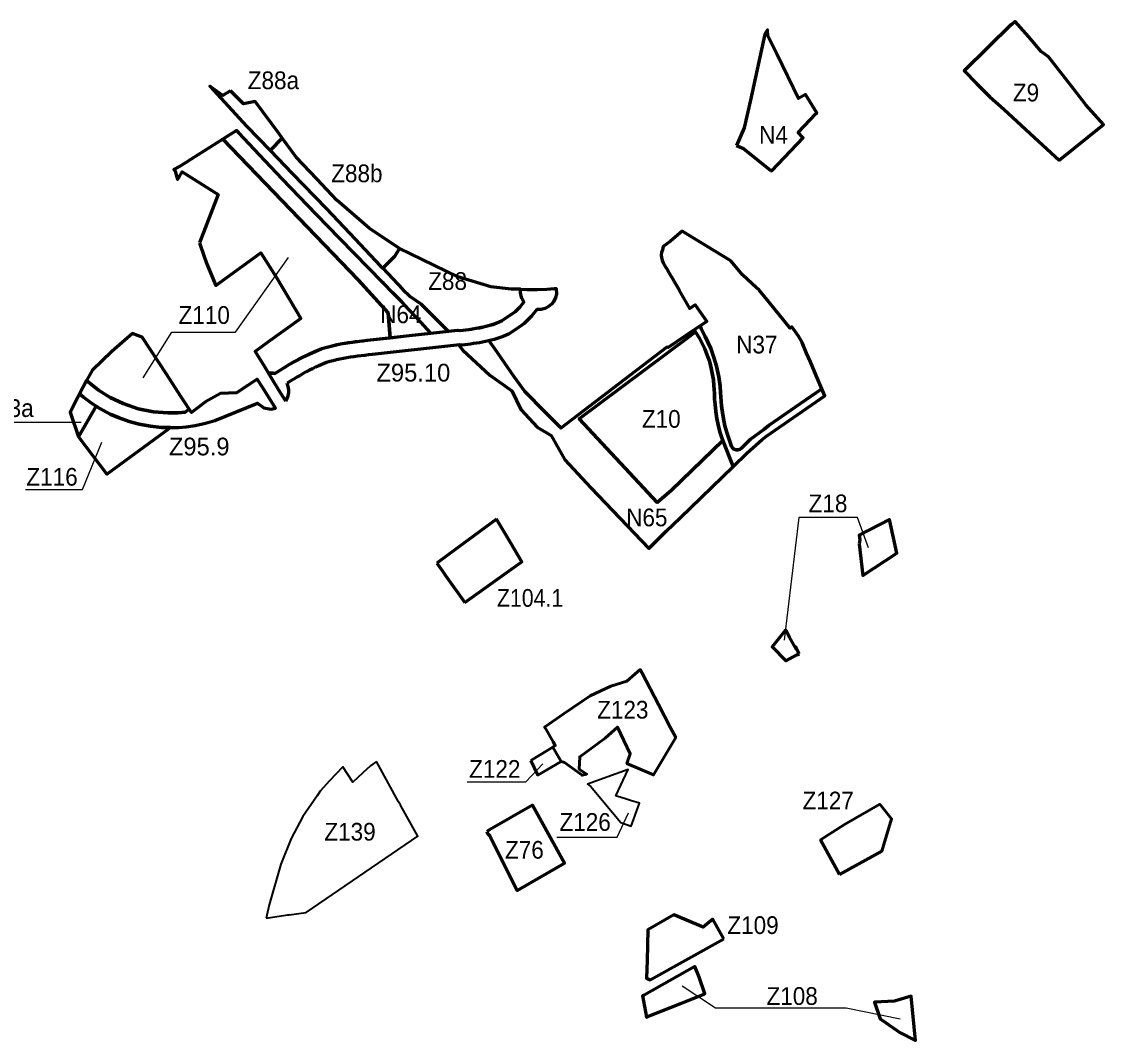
# Model space of a CAD drawing. Extents: x -650277 to -643425, y -1073980 to -1066720.
# Drawn here: x -647467 to -646003, y -1073134 to -1071755 of the extents above; entities that cross this region are included whole.
import ezdxf

# ---------------------------------------------------------------- set-up
doc = ezdxf.new("R2010")
doc.units = 0
doc.header["$LTSCALE"] = 9.6
for name, color, linetype, lineweight in [('1', 7, 'Continuous', 60), ('15', 7, 'Continuous', 60), ('18', 7, 'Continuous', 60), ('2', 7, 'Continuous', 40), ('24', 7, 'Continuous', 60), ('30', 7, 'Continuous', 60), ('34', 7, 'Continuous', 60), ('35', 7, 'Continuous', 60), ('40', 7, 'Continuous', 60), ('42', 7, 'Continuous', 60), ('45', 7, 'Continuous', 60), ('59', 7, 'Continuous', 25), ('60', 7, 'Continuous', 60), ('63', 7, 'Continuous', 25), ('7', 7, 'Continuous', 60)]:
    doc.layers.add(name, color=color, linetype=linetype, lineweight=lineweight)

msp = doc.modelspace()

# ---------------------------------------------------------------- linework, layer by layer
at = {"layer": '1'}
msp.add_line((-646417.787, -1072612.168), (-646414.77, -1072610.61), dxfattribs=at)
for points in [[(-646102.04, -1071906.4), (-646068.317, -1071937.555), (-646062.91, -1071942.55), (-646002.93, -1071893.984), (-646026.64, -1071867.44), (-646043.49, -1071845.87), (-646077.32, -1071802.59), (-646087, -1071795), (-646104.5, -1071774.86), (-646122.16, -1071754.78), (-646127.12, -1071759.15), (-646127.84, -1071758.53), (-646191.57, -1071821.44), (-646174.69, -1071838.69), (-646156.59, -1071856.53), (-646137.74, -1071873.31)], [(-646606.848, -1072405.785), (-646587.666, -1072389.082), (-646518.208, -1072321.92), (-646519.417, -1072318.408), (-646522.007, -1072309.932), (-646524.282, -1072300.849), (-646526, -1072292.201), (-646527.5, -1072282.657), (-646528.566, -1072273.308), (-646529.182, -1072265.941), (-646529.607, -1072258.124), (-646530.188, -1072247.442), (-646530.892, -1072239.747), (-646531.93, -1072232.861), (-646533.286, -1072226.031), (-646535.344, -1072217.844), (-646536.772, -1072213.218), (-646539.168, -1072206.122), (-646539.168, -1072206.122), (-646542.484, -1072197.985), (-646546.09, -1072190.428), (-646549.793, -1072183.38), (-646554.56, -1072175.629), (-646555.051, -1072174.933), (-646563.299, -1072181.091), (-646710.684, -1072291.133), (-646712.634, -1072292.59)], [(-646333.34, -1072461.67), (-646328.45, -1072504.81), (-646282.47, -1072474.34), (-646292.44, -1072428.89), (-646333.33, -1072450.12), (-646332.68, -1072456.19)]]:
    msp.add_lwpolyline(points, close=True, dxfattribs=at)
for points in [[(-647184.81, -1071848.61), (-647185.62, -1071849.12), (-647194.96, -1071854.93), (-647205.62, -1071847.24), (-647212.66, -1071842.15), (-647163.08, -1071896.13), (-647131.146, -1071929.146)], [(-647131.146, -1071929.146), (-647114.479, -1071912.479), (-647118.79, -1071906.59), (-647151.07, -1071863.08), (-647167.15, -1071866.22), (-647184.81, -1071848.61)], [(-646996.8, -1072034.35), (-647040.89, -1071996.58), (-647067.53, -1071967.54), (-647095.51, -1071938.39), (-647114.479, -1071912.479), (-647131.146, -1071929.146), (-647101.07, -1071960.24)], [(-647101.07, -1071960.24), (-647055.16, -1072007.74), (-647023.04, -1072041.63), (-646981.35, -1072085.77), (-646978.602, -1072088.66), (-646962.041, -1072072.379), (-646956.04, -1072061.95), (-646996.8, -1072034.35)], [(-646420.36, -1072601.78), (-646427.95, -1072588.07), (-646432.57, -1072579.75), (-646433.36, -1072578.45), (-646451.458, -1072601.008), (-646433.024, -1072620.04), (-646417.787, -1072612.168)], [(-646414.77, -1072610.61), (-646419.11, -1072602.03), (-646419.47, -1072601.31), (-646419.02, -1072604.18), (-646420.36, -1072601.78)]]:
    msp.add_lwpolyline(points, dxfattribs=at)
at = {"layer": '1', "lineweight": 53}
for points in [[(-646737.05, -1072756.4), (-646732.5, -1072757.63), (-646708.65, -1072775.02), (-646702.45, -1072773.39), (-646712.46, -1072766.76), (-646711.79, -1072750.02), (-646677.39, -1072724.85), (-646660.89, -1072709.97), (-646643.36, -1072746.04), (-646647.93, -1072759.01), (-646612.11, -1072774.56), (-646581.92, -1072723.91), (-646589.37, -1072709.83), (-646605.23, -1072679.37), (-646627.32, -1072636.95), (-646629.86, -1072632.07), (-646648.27, -1072647.48), (-646669.6, -1072654.53), (-646697.89, -1072667.65)], [(-646697.89, -1072667.65), (-646732.95, -1072691.68), (-646759.491, -1072709.878), (-646757.5, -1072713.3), (-646747.87, -1072729.85), (-646744.94, -1072734.88), (-646748.3, -1072737.01), (-646737.05, -1072756.4)]]:
    msp.add_lwpolyline(points, dxfattribs=at)
for points in [[(-646778.2, -1072755.19), (-646755.1, -1072741.28), (-646748.3, -1072737.01), (-646737.05, -1072756.4), (-646768.74, -1072774.78)], [(-646360.22, -1072909.57), (-646303.02, -1072877.74), (-646289.63, -1072834.04), (-646305.56, -1072814.43), (-646353.25, -1072841.63), (-646385.86, -1072862.59)]]:
    msp.add_lwpolyline(points, close=True, dxfattribs=at)
at = {"layer": '1', "lineweight": 25}
msp.add_lwpolyline([(-646864.278, -1072783.783), (-646784.878, -1072783.783), (-646761.687, -1072759.411)], dxfattribs=at)
at = {"layer": '1', "lineweight": 40}
for points in [[(-646653.02, -1072806.07), (-646663.07, -1072803.04), (-646663.07, -1072803.04), (-646646.12, -1072767.32), (-646646.31, -1072767.388), (-646701.12, -1072787.08), (-646697.09, -1072790.03), (-646656.36, -1072839.08)], [(-646656.36, -1072839.08), (-646642.404, -1072844.195), (-646631.08, -1072812.68), (-646643.01, -1072809.08), (-646651.11, -1072806.64), (-646653.02, -1072806.07)]]:
    msp.add_lwpolyline(points, dxfattribs=at)
at = {"layer": '15'}
msp.add_lwpolyline([(-646529.182, -1072265.941), (-646528.566, -1072273.308), (-646527.5, -1072282.657), (-646526, -1072292.201), (-646524.282, -1072300.849), (-646522.007, -1072309.932), (-646519.417, -1072318.408), (-646518.208, -1072321.92), (-646504.244, -1072357.026), (-646485.656, -1072338.908), (-646473.069, -1072327.765), (-646465.227, -1072321.127), (-646459.03, -1072316.137), (-646380.12, -1072261.44), (-646384.056, -1072252.138), (-646420.085, -1072276.737), (-646455.557, -1072301.131), (-646462.79, -1072306.784), (-646480.923, -1072320.667), (-646486.273, -1072325.526), (-646492.813, -1072332.07), (-646494.794, -1072333.558), (-646497.569, -1072334.55), (-646500.244, -1072334.45), (-646503.018, -1072333.459), (-646504.802, -1072331.971), (-646506.189, -1072329.889), (-646509.954, -1072319.377), (-646512.729, -1072311.048), (-646515.305, -1072301.925), (-646516.692, -1072294.983), (-646518.079, -1072287.051), (-646519.756, -1072274.861), (-646521.051, -1072256.707), (-646521.646, -1072248.378), (-646523.628, -1072235.883), (-646526.798, -1072221.011), (-646530.167, -1072209.31), (-646534.527, -1072197.411), (-646541.822, -1072181.102), (-646547.606, -1072170.835), (-646548.676, -1072166.737), (-646556.693, -1072172.16), (-646555.051, -1072174.933), (-646554.56, -1072175.629), (-646549.793, -1072183.38), (-646546.09, -1072190.428), (-646542.484, -1072197.985), (-646539.168, -1072206.122), (-646536.772, -1072213.218), (-646535.344, -1072217.844), (-646533.286, -1072226.031), (-646531.93, -1072232.861), (-646530.892, -1072239.747), (-646530.188, -1072247.442), (-646529.607, -1072258.124)], close=True, dxfattribs=at)
at = {"layer": '18'}
msp.add_lwpolyline([(-646837.81, -1072851.3), (-646836.5, -1072853.76), (-646833.67, -1072857.15), (-646824.89, -1072874.66), (-646796.68, -1072930.92), (-646732.28, -1072894.29), (-646775.85, -1072815.39), (-646834.08, -1072849.15)], close=True, dxfattribs=at)
at = {"layer": '2'}
for points in [[(-646987.154, -1072756.377), (-646995.02, -1072762.45), (-647005.249, -1072771.938), (-647019.06, -1072784.57), (-647032.7, -1072763.68), (-647050.492, -1072782.771)], [(-646954.7, -1072815.232), (-646957.105, -1072810.92), (-646987.154, -1072756.377)], [(-647050.492, -1072782.771), (-647063.04, -1072796.74), (-647067.22, -1072802.77), (-647086.65, -1072830.76), (-647102.38, -1072860.7), (-647116.33, -1072895.3)], [(-647136.39, -1072968.63), (-647110.32, -1072964.56), (-647107.01, -1072964.04), (-647105.4, -1072963.84), (-647082.36, -1072960.95), (-646931.1, -1072857.55), (-646954.51, -1072815.63), (-646954.7, -1072815.232)], [(-647116.33, -1072895.3), (-647132.47, -1072950.4), (-647136.39, -1072968.63)]]:
    msp.add_lwpolyline(points, dxfattribs=at)
at = {"layer": '24'}
for points in [[(-647226.41, -1072054.11), (-647219.64, -1072074.29), (-647216.23, -1072084.14), (-647204.78, -1072110.92), (-647204.38, -1072111.87), (-647143.76, -1072067.69), (-647122.33, -1072101.34), (-647089.54, -1072156.53), (-647134.17, -1072188.95), (-647151.05, -1072201.21), (-647138.65, -1072221.5), (-647133, -1072230.754), (-647124.81, -1072231.168), (-647104.989, -1072219.005), (-647082.249, -1072206.591), (-647060.973, -1072197.439), (-647035.515, -1072191.104), (-647010.148, -1072187.308), (-646995.137, -1072185.597), (-646968.503, -1072182.672), (-646971.283, -1072148.82), (-647011.762, -1072104.502), (-647194.903, -1071913.941), (-647238.1, -1071941), (-647245.71, -1071945.77), (-647253.67, -1071950.76), (-647261.12, -1071954.82), (-647259.7, -1071957.06), (-647256.53, -1071968.64), (-647253.85, -1071964.38), (-647249.92, -1071958.12), (-647201.53, -1071988.71)], [(-647390.58, -1072316.75), (-647366.505, -1072275.41), (-647372.858, -1072271.363), (-647383.813, -1072263.219), (-647389.072, -1072258.845), (-647391.3, -1072263.04), (-647401.88, -1072283.4)], [(-647390.58, -1072316.75), (-647351.86, -1072367.52), (-647269.52, -1072307.17), (-647265.793, -1072304.439), (-647271.395, -1072304.452), (-647278.108, -1072304.147), (-647292.715, -1072302.646), (-647308.157, -1072299.786), (-647321.953, -1072296.073), (-647335.382, -1072291.341), (-647347.369, -1072286.111), (-647361.521, -1072278.584), (-647366.505, -1072275.41)]]:
    msp.add_lwpolyline(points, close=True, dxfattribs=at)
msp.add_arc((-646767.624, -1072120.384), 24.428, 264.28146, 264.89913, dxfattribs=at)
at = {"layer": '30'}
for points in [[(-646824.42, -1072428.58), (-646878.91, -1072468.54), (-646905.18, -1072487.8)], [(-646867.283, -1072540.984), (-646791.569, -1072487.198), (-646790.354, -1072486.136), (-646810.77, -1072451.09), (-646824.42, -1072428.58)], [(-646905.18, -1072487.8), (-646898.1, -1072498.02), (-646893.64, -1072504.45), (-646867.283, -1072540.984)]]:
    msp.add_lwpolyline(points, dxfattribs=at)
at = {"layer": '34'}
for points in [[(-646574.156, -1073083.691), (-646542.62, -1073071.1), (-646550.01, -1073048.55), (-646552.79, -1073041.53), (-646555.79, -1073033.92), (-646624.69, -1073072.66), (-646626.967, -1073073.918), (-646621.38, -1073102.66), (-646620.19, -1073102.14), (-646618.56, -1073101.42)], [(-646298.029, -1073109.723), (-646278.38, -1073123.25), (-646257.09, -1073134.01), (-646262.94, -1073074.15), (-646285.77, -1073081.01), (-646312.87, -1073082.4), (-646305.18, -1073104.8)]]:
    msp.add_lwpolyline(points, close=True, dxfattribs=at)
at = {"layer": '35'}
for points in [[(-647246.563, -1072270.214), (-647251.85, -1072262.12), (-647271.38, -1072232.23), (-647304.32, -1072181.81), (-647310.33, -1072179.58), (-647317.33, -1072176.99), (-647345.42, -1072201.58), (-647372.1, -1072226.89), (-647375.551, -1072233.387), (-647379.422, -1072240.675), (-647363.317, -1072253.632), (-647347.382, -1072263.623), (-647330.032, -1072271.935), (-647309.416, -1072278.875), (-647288.769, -1072283.003), (-647269.579, -1072284.489), (-647255.671, -1072284.192), (-647246.206, -1072283.328), (-647240.55, -1072279.42)], [(-646516.7, -1072996.65), (-646531.46, -1072970.12), (-646544.68, -1072980.62), (-646584.23, -1072964.22), (-646619.48, -1072984.34), (-646620.71, -1073025.49), (-646621.44, -1073049.79), (-646616.55, -1073052.21)]]:
    msp.add_lwpolyline(points, close=True, dxfattribs=at)
at = {"layer": '40'}
msp.add_lwpolyline([(-646507.28, -1072078.4), (-646530.073, -1072064.559), (-646573.05, -1072038.46), (-646588.75, -1072052.06), (-646598.827, -1072059.244), (-646599.86, -1072063.71), (-646601, -1072067.55), (-646601.42, -1072071.01), (-646601.16, -1072074.07), (-646600.8, -1072075.94), (-646600.22, -1072077.86), (-646598.67, -1072081.55), (-646595.86, -1072086.82), (-646593.13, -1072091.01), (-646591.02, -1072094.4), (-646585.08, -1072104.81), (-646583.9, -1072106.42), (-646577.41, -1072117.76), (-646577.08, -1072118.7), (-646563.11, -1072143.03), (-646555.49, -1072138.17), (-646539.94, -1072160.83), (-646548.676, -1072166.737), (-646547.606, -1072170.835), (-646541.822, -1072181.102), (-646534.527, -1072197.411), (-646530.167, -1072209.31), (-646526.798, -1072221.011), (-646523.628, -1072235.883), (-646521.646, -1072248.378), (-646521.051, -1072256.707), (-646519.756, -1072274.861), (-646518.079, -1072287.051), (-646516.692, -1072294.983), (-646515.305, -1072301.925), (-646512.729, -1072311.048), (-646509.954, -1072319.377), (-646506.189, -1072329.889), (-646504.802, -1072331.971), (-646503.018, -1072333.459), (-646500.244, -1072334.45), (-646497.569, -1072334.55), (-646494.794, -1072333.558), (-646492.813, -1072332.07), (-646486.273, -1072325.526), (-646480.923, -1072320.667), (-646462.79, -1072306.784), (-646455.557, -1072301.131), (-646420.085, -1072276.737), (-646384.056, -1072252.138), (-646391.77, -1072233.91), (-646399.6, -1072215.39), (-646404.67, -1072203.42), (-646410.68, -1072189.36), (-646415.84, -1072180.43), (-646424.56, -1072167.96), (-646426.98, -1072169.74), (-646455.75, -1072134.29), (-646468.35, -1072118.76), (-646469.41, -1072117.44), (-646472.72, -1072115.38), (-646491.69, -1072097.45)], close=True, dxfattribs=at)
at = {"layer": '42'}
msp.add_lwpolyline([(-647011.762, -1072104.502), (-646971.283, -1072148.82), (-646968.503, -1072182.672), (-646942.928, -1072179.864), (-646913.373, -1072176.618), (-646931.653, -1072156.802), (-646942.78, -1072144.74), (-646952.48, -1072134.22), (-646964.8, -1072121.83), (-646977.59, -1072108.96), (-646978.45, -1072108.09), (-647036.8, -1072048.41), (-647068.31, -1072015.68), (-647114.59, -1071967.77), (-647145.38, -1071935), (-647173.14, -1071905.45), (-647174.57, -1071904.06), (-647176.32, -1071902.3), (-647194.903, -1071913.941)], close=True, dxfattribs=at)
at = {"layer": '45'}
msp.add_lwpolyline([(-646594.606, -1072444.422), (-646575.792, -1072426.789), (-646504.244, -1072357.026), (-646518.208, -1072321.92), (-646587.666, -1072389.082), (-646606.848, -1072405.785), (-646712.634, -1072292.59), (-646563.299, -1072181.091), (-646555.051, -1072174.933), (-646556.693, -1072172.16), (-646592.2, -1072196.17), (-646593.85, -1072195.48), (-646643.55, -1072233.5), (-646737.449, -1072305.019), (-646738.951, -1072303.49), (-646758.684, -1072283.41), (-646785.958, -1072255.505), (-646800.76, -1072235.668), (-646826.893, -1072197.582), (-646832.718, -1072189.697), (-646834.279, -1072186.818), (-646833.373, -1072186.562), (-646835.538, -1072187.097), (-646839.556, -1072187.988), (-646843.569, -1072188.789), (-646847.575, -1072189.507), (-646851.567, -1072190.155), (-646855.545, -1072190.741), (-646859.506, -1072191.276), (-646863.448, -1072191.771), (-646867.371, -1072192.234), (-646871.271, -1072192.675), (-646874.517, -1072192.471), (-646875.509, -1072192.58), (-646870.21, -1072199.51), (-646833.75, -1072233.32), (-646803.98, -1072254.74), (-646791.59, -1072279.78), (-646769.24, -1072303.65), (-646750.58, -1072315.02), (-646750.12, -1072315.82), (-646742.32, -1072329.62), (-646731.82, -1072348.2), (-646696.83, -1072385.81), (-646618.158, -1072468.098)], close=True, dxfattribs=at)
at = {"layer": '60'}
msp.add_line((-646978.602, -1072088.66), (-646951.95, -1072116.84), dxfattribs=at)
for points in [[(-646790.432, -1072129.195), (-646791.977, -1072122.305), (-646791.84, -1072117.172), (-646804.27, -1072116.98), (-646832.01, -1072113.66), (-646876.83, -1072100.12), (-646941.054, -1072069.172), (-646956.04, -1072061.95), (-646962.041, -1072072.379), (-646978.602, -1072088.66)], [(-646951.95, -1072116.84), (-646941.45, -1072126.84), (-646927.14, -1072136.74), (-646891.05, -1072172.79), (-646890.044, -1072174.056), (-646876.712, -1072172.592), (-646873.495, -1072172.799), (-646862.09, -1072171.444), (-646840.102, -1072167.623), (-646825.169, -1072163.164), (-646816.74, -1072159.571), (-646799, -1072147), (-646792.58, -1072140.847), (-646787.481, -1072134.643), (-646790.432, -1072129.195)], [(-646816.74, -1072159.571), (-646799, -1072147), (-646792.58, -1072140.847), (-646787.481, -1072134.643), (-646790.343, -1072129.36), (-646791.977, -1072122.305), (-646791.84, -1072117.172), (-646783.449, -1072117.302), (-646769.668, -1072117.517), (-646756.298, -1072117), (-646746.547, -1072116.221), (-646743.596, -1072115.985), (-646743.411, -1072123.612), (-646744.554, -1072128.415), (-646747.39, -1072134.069), (-646750.164, -1072137.467), (-646753.929, -1072140.612), (-646758.736, -1072143.137), (-646763.959, -1072144.535), (-646770.057, -1072144.677), (-646777.129, -1072153.576), (-646787.223, -1072163.402), (-646797.713, -1072171.151), (-646808.466, -1072177.78)], [(-647124.81, -1072231.168), (-647113.646, -1072224.274), (-647109.342, -1072221.634), (-647104.989, -1072219.005), (-647100.583, -1072216.405), (-647096.114, -1072213.845), (-647091.574, -1072211.346), (-647086.955, -1072208.921), (-647082.249, -1072206.591), (-647077.456, -1072204.373), (-647072.72, -1072202.352), (-647060.973, -1072197.439), (-647055.906, -1072195.893), (-647050.82, -1072194.5), (-647045.722, -1072193.245), (-647040.618, -1072192.117), (-647035.515, -1072191.104), (-647030.417, -1072190.192), (-647025.33, -1072189.37), (-647020.254, -1072188.623), (-647015.192, -1072187.939), (-647010.148, -1072187.308), (-647005.124, -1072186.715), (-647000.12, -1072186.148), (-646995.137, -1072185.597), (-646876.712, -1072172.592), (-646873.495, -1072172.799), (-646869.667, -1072172.366), (-646865.866, -1072171.917), (-646862.09, -1072171.444), (-646858.343, -1072170.937), (-646854.627, -1072170.389), (-646850.941, -1072169.791), (-646847.291, -1072169.137), (-646843.678, -1072168.416), (-646840.102, -1072167.623), (-646836.573, -1072166.751), (-646833.091, -1072165.791), (-646829.66, -1072164.739), (-646826.287, -1072163.588), (-646822.975, -1072162.332), (-646819.733, -1072160.968), (-646816.74, -1072159.571)], [(-646808.466, -1072177.78), (-646811.621, -1072179.254), (-646815.549, -1072180.906), (-646819.509, -1072182.408), (-646823.496, -1072183.769), (-646827.501, -1072184.997), (-646831.517, -1072186.103), (-646835.538, -1072187.097), (-646839.556, -1072187.988), (-646843.569, -1072188.789), (-646847.575, -1072189.507), (-646851.567, -1072190.155), (-646855.545, -1072190.741), (-646859.506, -1072191.276), (-646863.448, -1072191.771), (-646867.371, -1072192.234), (-646871.271, -1072192.675), (-646874.517, -1072192.471), (-646992.937, -1072205.475), (-646997.894, -1072206.024), (-647002.826, -1072206.583), (-647007.734, -1072207.162), (-647012.612, -1072207.773), (-647017.46, -1072208.427), (-647022.278, -1072209.136), (-647027.061, -1072209.91), (-647031.807, -1072210.758), (-647036.512, -1072211.693), (-647041.174, -1072212.723), (-647045.786, -1072213.858), (-647050.344, -1072215.107), (-647054.841, -1072216.479), (-647064.868, -1072220.746), (-647069.33, -1072222.651), (-647073.611, -1072224.631), (-647077.867, -1072226.739), (-647082.102, -1072228.962), (-647086.322, -1072231.285), (-647090.531, -1072233.695), (-647094.737, -1072236.177), (-647098.944, -1072238.718), (-647103.164, -1072241.306), (-647108.131, -1072244.373)], [(-647109.812, -1072268.588), (-647110.55, -1072267.42), (-647119.07, -1072253.56), (-647128.07, -1072238.83), (-647133, -1072230.754)]]:
    msp.add_lwpolyline(points, dxfattribs=at)
msp.add_lwpolyline([(-647265.793, -1072304.439), (-647255.16, -1072304.123), (-647244.428, -1072303.192), (-647232.368, -1072301.4), (-647218.5, -1072298.335), (-647205.975, -1072294.599), (-647148.171, -1072271.47), (-647139.697, -1072277.484), (-647130.12, -1072279.44), (-647123.774, -1072277.899), (-647141.05, -1072250.54), (-647148.71, -1072238.76), (-647148.71, -1072238.76), (-647160.91, -1072246.82), (-647176.7, -1072257.24), (-647198.3, -1072258.09), (-647218.35, -1072269.67), (-647237.6, -1072283.78), (-647240.55, -1072279.42), (-647246.206, -1072283.328), (-647255.671, -1072284.192), (-647269.579, -1072284.489), (-647288.769, -1072283.003), (-647309.416, -1072278.875), (-647330.032, -1072271.935), (-647347.382, -1072263.623), (-647363.317, -1072253.632), (-647379.422, -1072240.675), (-647389.072, -1072258.845), (-647383.813, -1072263.219), (-647372.858, -1072271.363), (-647361.521, -1072278.584), (-647347.369, -1072286.111), (-647335.382, -1072291.341), (-647321.953, -1072296.073), (-647308.157, -1072299.786), (-647292.715, -1072302.646), (-647278.108, -1072304.147), (-647271.395, -1072304.452), (-647265.793, -1072304.439)], close=True, dxfattribs=at)
for start, end in [(77.44425, 96.77054), (326.23773, 25.81772)]:
    msp.add_arc((-647130.12, -1072255.012), 24.428, start, end, dxfattribs=at)
at = {"layer": '63'}
msp.add_line((-647525, -1072297), (-647387, -1072297), dxfattribs=at)
for points in [[(-647303, -1072237), (-647264, -1072175), (-647178, -1072175), (-647106, -1072074)], [(-647462, -1072388), (-647385, -1072388), (-647359, -1072324)], [(-646321, -1072467), (-646336, -1072426), (-646415, -1072426), (-646435, -1072592)], [(-646743, -1072859), (-646661, -1072859), (-646646, -1072826)], [(-646573, -1073060), (-646528, -1073090), (-646351, -1073090), (-646278, -1073105)]]:
    msp.add_lwpolyline(points, dxfattribs=at)
at = {"layer": '7'}
for points in [[(-646453.04, -1071956.3), (-646451.87, -1071956.88), (-646409.4, -1071912.17), (-646416.2, -1071904.81), (-646391.83, -1071879.32), (-646390.732, -1071878.171), (-646405.99, -1071853.26), (-646415.46, -1071859.05), (-646445.115, -1071798.418), (-646456.96, -1071774.2), (-646457.52, -1071765.98), (-646461.09, -1071771.76), (-646480.81, -1071861.18), (-646489.34, -1071898.61), (-646499.741, -1071922.455)], [(-646499.741, -1071922.455), (-646490.111, -1071926.754), (-646453.04, -1071956.3)]]:
    msp.add_lwpolyline(points, dxfattribs=at)

# ---------------------------------------------------------------- texts
at = {"layer": '59', "width": 0.95}
msp.add_text('Z139', height=24, dxfattribs=at).set_placement((-647057.605, -1072863.534))
at = {"layer": '63'}
for s, width, p in [('Z88a', 0.95, (-647161.291, -1071846.187)), ('Z9', 0.95, (-646125.48, -1071862.818)), ('N4', 0.95, (-646469, -1071920)), ('Z88b', 0.95, (-647048.291, -1071972.187)), ('Z88', 0.95, (-646917, -1072118)), ('Z110', 0.95, (-647255, -1072164)), ('N64', 0.95, (-646982, -1072163)), ('N37', 0.95, (-646500, -1072204)), ('N63a', 0.95, (-647524, -1072290)), ('Z10', 0.95, (-646627.672, -1072304.645)), ('Z116', 0.95, (-647461, -1072383)), ('Z18', 0.95, (-646402, -1072419)), ('N65', 0.95, (-646649, -1072438)), ('Z104.1', 0.9, (-646824, -1072547)), ('Z123', 0.95, (-646688.261, -1072698.34)), ('Z122', 0.95, (-646861.605, -1072778.534)), ('Z127', 0.95, (-646410.261, -1072821.34)), ('Z126', 0.95, (-646739.261, -1072850.34)), ('Z76', 0.95, (-646813, -1072888)), ('Z109', 0.95, (-646512, -1072990)), ('Z108', 0.95, (-646459, -1073086))]:
    msp.add_text(s, height=24, dxfattribs=dict(at, width=width)).set_placement(p)
for s, p in [('Z95.10', (-646987, -1072242)), ('Z95.9', (-647268, -1072342))]:
    msp.add_text(s, height=24, dxfattribs=at).set_placement(p)

doc.saveas('drawing.dxf')
